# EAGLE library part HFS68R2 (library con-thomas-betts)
THOMAS&BETTS
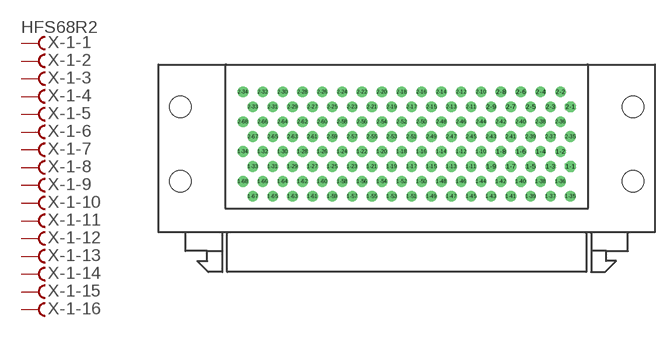
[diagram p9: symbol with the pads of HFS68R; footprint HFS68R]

Designator prefix X; gates -1-1=FV -1-2=F -1-3=F -1-4=F -1-5=F -1-6=F -1-7=F -1-8=F -1-9=F -1-10=F -1-11=F -1-12=F -1-13=F -1-14=F -1-15=F -1-16=F -1-17=F -1-18=F -1-19=F -1-20=F -1-21=F -1-22=F -1-23=F -1-24=F -1-25=F -1-26=F -1-27=F -1-28=F -1-29=F -1-30=F -1-31=F -1-32=F -1-33=F -1-34=F -1-35=F -1-36=F -1-37=F -1-38=F -1-39=F -1-40=F -1-41=F -1-42=F -1-43=F -1-44=F -1-45=F -1-46=F -1-47=F -1-48=F -1-49=F -1-50=F -1-51=F -1-52=F -1-53=F -1-54=F -1-55=F -1-56=F -1-57=F -1-58=F -1-59=F -1-60=F -1-61=F -1-62=F -1-63=F -1-64=F -1-65=F -1-66=F -1-67=F -1-68=F -2-1=FV -2-2=F -2-3=F -2-4=F -2-5=F -2-6=F -2-7=F -2-8=F -2-9=F -2-10=F -2-11=F -2-12=F -2-13=F -2-14=F -2-15=F -2-16=F -2-17=F -2-18=F -2-19=F -2-20=F -2-21=F -2-22=F -2-23=F -2-24=F -2-25=F -2-26=F -2-27=F -2-28=F -2-29=F -2-30=F -2-31=F -2-32=F -2-33=F -2-34=F -2-35=F -2-36=F -2-37=F -2-38=F -2-39=F -2-40=F -2-41=F -2-42=F -2-43=F -2-44=F -2-45=F -2-46=F -2-47=F -2-48=F -2-49=F -2-50=F -2-51=F -2-52=F -2-53=F -2-54=F -2-55=F -2-56=F -2-57=F -2-58=F -2-59=F -2-60=F -2-61=F -2-62=F -2-63=F -2-64=F -2-65=F -2-66=F -2-67=F -2-68=F

## HFS68R2 (OC_FARNELL: unknown; OC_NEWARK: unknown)  [HFS68R]
1-1  -1-1:F  pas
1-2  -1-2:F  pas
1-3  -1-3:F  pas
1-4  -1-4:F  pas
1-5  -1-5:F  pas
1-6  -1-6:F  pas
1-7  -1-7:F  pas
1-8  -1-8:F  pas
1-9  -1-9:F  pas
1-10  -1-10:F  pas
1-11  -1-11:F  pas
1-12  -1-12:F  pas
1-13  -1-13:F  pas
1-14  -1-14:F  pas
1-15  -1-15:F  pas
1-16  -1-16:F  pas
1-17  -1-17:F  pas
1-18  -1-18:F  pas
1-19  -1-19:F  pas
1-20  -1-20:F  pas
1-21  -1-21:F  pas
1-22  -1-22:F  pas
1-23  -1-23:F  pas
1-24  -1-24:F  pas
1-25  -1-25:F  pas
1-26  -1-26:F  pas
1-27  -1-27:F  pas
1-28  -1-28:F  pas
1-29  -1-29:F  pas
1-30  -1-30:F  pas
1-31  -1-31:F  pas
1-32  -1-32:F  pas
1-33  -1-33:F  pas
1-34  -1-34:F  pas
1-35  -1-35:F  pas
1-36  -1-36:F  pas
1-37  -1-37:F  pas
1-38  -1-38:F  pas
1-39  -1-39:F  pas
1-40  -1-40:F  pas
1-41  -1-41:F  pas
1-42  -1-42:F  pas
1-43  -1-43:F  pas
1-44  -1-44:F  pas
1-45  -1-45:F  pas
1-46  -1-46:F  pas
1-47  -1-47:F  pas
1-48  -1-48:F  pas
1-49  -1-49:F  pas
1-50  -1-50:F  pas
1-51  -1-51:F  pas
1-52  -1-52:F  pas
1-53  -1-53:F  pas
1-54  -1-54:F  pas
1-55  -1-55:F  pas
1-56  -1-56:F  pas
1-57  -1-57:F  pas
1-58  -1-58:F  pas
1-59  -1-59:F  pas
1-60  -1-60:F  pas
1-61  -1-61:F  pas
1-62  -1-62:F  pas
1-63  -1-63:F  pas
1-64  -1-64:F  pas
1-65  -1-65:F  pas
1-66  -1-66:F  pas
1-67  -1-67:F  pas
1-68  -1-68:F  pas
2-1  -2-1:F  pas
2-2  -2-2:F  pas
2-3  -2-3:F  pas
2-4  -2-4:F  pas
2-5  -2-5:F  pas
2-6  -2-6:F  pas
2-7  -2-7:F  pas
2-8  -2-8:F  pas
2-9  -2-9:F  pas
2-10  -2-10:F  pas
2-11  -2-11:F  pas
2-12  -2-12:F  pas
2-13  -2-13:F  pas
2-14  -2-14:F  pas
2-15  -2-15:F  pas
2-16  -2-16:F  pas
2-17  -2-17:F  pas
2-18  -2-18:F  pas
2-19  -2-19:F  pas
2-20  -2-20:F  pas
2-21  -2-21:F  pas
2-22  -2-22:F  pas
2-23  -2-23:F  pas
2-24  -2-24:F  pas
2-25  -2-25:F  pas
2-26  -2-26:F  pas
2-27  -2-27:F  pas
2-28  -2-28:F  pas
2-29  -2-29:F  pas
2-30  -2-30:F  pas
2-31  -2-31:F  pas
2-32  -2-32:F  pas
2-33  -2-33:F  pas
2-34  -2-34:F  pas
2-35  -2-35:F  pas
2-36  -2-36:F  pas
2-37  -2-37:F  pas
2-38  -2-38:F  pas
2-39  -2-39:F  pas
2-40  -2-40:F  pas
2-41  -2-41:F  pas
2-42  -2-42:F  pas
2-43  -2-43:F  pas
2-44  -2-44:F  pas
2-45  -2-45:F  pas
2-46  -2-46:F  pas
2-47  -2-47:F  pas
2-48  -2-48:F  pas
2-49  -2-49:F  pas
2-50  -2-50:F  pas
2-51  -2-51:F  pas
2-52  -2-52:F  pas
2-53  -2-53:F  pas
2-54  -2-54:F  pas
2-55  -2-55:F  pas
2-56  -2-56:F  pas
2-57  -2-57:F  pas
2-58  -2-58:F  pas
2-59  -2-59:F  pas
2-60  -2-60:F  pas
2-61  -2-61:F  pas
2-62  -2-62:F  pas
2-63  -2-63:F  pas
2-64  -2-64:F  pas
2-65  -2-65:F  pas
2-66  -2-66:F  pas
2-67  -2-67:F  pas
2-68  -2-68:F  pas

## Footprint HFS68R (pad centres in mm)
THOMAS&BETTS Fine Pitch "D" Connector HFS68Rx29x
drill 0.864 octagon: 1-1 20.955,6.96; 2-1 20.955,14.6
drill 0.864 round: 1-2 19.685,8.87; 1-3 18.415,6.96; 1-4 17.145,8.87; 1-5 15.875,6.96; 1-6 14.605,8.87; 1-7 13.335,6.96; 1-8 12.065,8.87; 1-9 10.795,6.96; 1-10 9.525,8.87; 1-11 8.255,6.96; 1-12 6.985,8.87; 1-13 5.715,6.96; 1-14 4.445,8.87; 1-15 3.175,6.96; 1-16 1.905,8.87; 1-17 0.635,6.96; 1-18 -0.635,8.87; 1-19 -1.905,6.96; 1-20 -3.175,8.87; 1-21 -4.445,6.96; 1-22 -5.715,8.87; 1-23 -6.985,6.96; 1-24 -8.255,8.87; 1-25 -9.525,6.96; 1-26 -10.795,8.87; 1-27 -12.065,6.96; 1-28 -13.335,8.87; 1-29 -14.605,6.96; 1-30 -15.875,8.87; 1-31 -17.145,6.96; 1-32 -18.415,8.87; 1-33 -19.685,6.96; 1-34 -20.955,8.87; 1-35 20.955,3.14; 1-36 19.685,5.05; 1-37 18.415,3.14; 1-38 17.145,5.05; 1-39 15.875,3.14; 1-40 14.605,5.05; 1-41 13.335,3.14; 1-42 12.065,5.05; 1-43 10.795,3.14; 1-44 9.525,5.05; 1-45 8.255,3.14; 1-46 6.985,5.05; 1-47 5.715,3.14; 1-48 4.445,5.05; 1-49 3.175,3.14; 1-50 1.905,5.05; 1-51 0.635,3.14; 1-52 -0.635,5.05; 1-53 -1.905,3.14; 1-54 -3.175,5.05; 1-55 -4.445,3.14; 1-56 -5.715,5.05; 1-57 -6.985,3.14; 1-58 -8.255,5.05; 1-59 -9.525,3.14; 1-60 -10.795,5.05; 1-61 -12.065,3.14; 1-62 -13.335,5.05; 1-63 -14.605,3.14; 1-64 -15.875,5.05; 1-65 -17.145,3.14; 1-66 -18.415,5.05; 1-67 -19.685,3.14; 1-68 -20.955,5.05; 2-2 19.685,16.51; 2-3 18.415,14.6; 2-4 17.145,16.51; 2-5 15.875,14.6; 2-6 14.605,16.51; 2-7 13.335,14.6; 2-8 12.065,16.51; 2-9 10.795,14.6; 2-10 9.525,16.51; 2-11 8.255,14.6; 2-12 6.985,16.51; 2-13 5.715,14.6; 2-14 4.445,16.51; 2-15 3.175,14.6; 2-16 1.905,16.51; 2-17 0.635,14.6; 2-18 -0.635,16.51; 2-19 -1.905,14.6; 2-20 -3.175,16.51; 2-21 -4.445,14.6; 2-22 -5.715,16.51; 2-23 -6.985,14.6; 2-24 -8.255,16.51; 2-25 -9.525,14.6; 2-26 -10.795,16.51; 2-27 -12.065,14.6; 2-28 -13.335,16.51; 2-29 -14.605,14.6; 2-30 -15.875,16.51; 2-31 -17.145,14.6; 2-32 -18.415,16.51; 2-33 -19.685,14.6; 2-34 -20.955,16.51; 2-35 20.955,10.78; 2-36 19.685,12.69; 2-37 18.415,10.78; 2-38 17.145,12.69; 2-39 15.875,10.78; 2-40 14.605,12.69; 2-41 13.335,10.78; 2-42 12.065,12.69; 2-43 10.795,10.78; 2-44 9.525,12.69; 2-45 8.255,10.78; 2-46 6.985,12.69; 2-47 5.715,10.78; 2-48 4.445,12.69; 2-49 3.175,10.78; 2-50 1.905,12.69; 2-51 0.635,10.78; 2-52 -0.635,12.69; 2-53 -1.905,10.78; 2-54 -3.175,12.69; 2-55 -4.445,10.78; 2-56 -5.715,12.69; 2-57 -6.985,10.78; 2-58 -8.255,12.69; 2-59 -9.525,10.78; 2-60 -10.795,12.69; 2-61 -12.065,10.78; 2-62 -13.335,12.69; 2-63 -14.605,10.78; 2-64 -15.875,12.69; 2-65 -17.145,10.78; 2-66 -18.415,12.69; 2-67 -19.685,10.78; 2-68 -20.955,12.69
hole 2.769 at 28.956,5.05
hole 2.769 at -28.956,5.05
hole 2.769 at 28.956,14.6
hole 2.769 at -28.956,14.6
